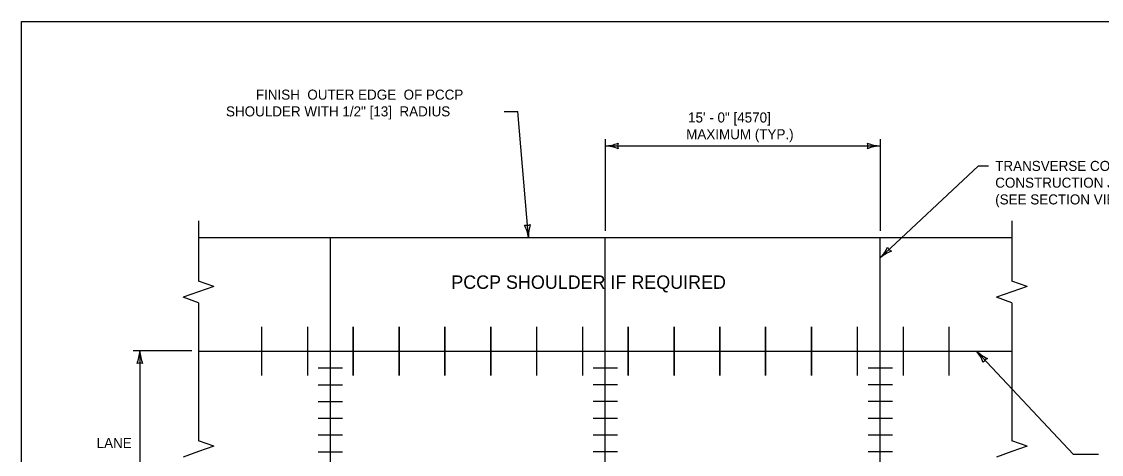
# Model space of a CAD drawing. Extents: x 49979.1 to 50021, y 49966.7 to 50011.4.
# Drawn here: x 49999.38 to 50005.83, y 49996.41 to 49999 of the extents above; entities that cross this region are included whole.
import ezdxf

# ---------------------------------------------------------------- set-up
doc = ezdxf.new("R2010")
doc.units = 0
for name, color, linetype in [('Level 1', 7, 'Continuous'), ('Level 2', 7, 'Continuous'), ('Level 20', 7, 'Continuous'), ('Level 3', 7, 'Continuous'), ('Level 4', 7, 'Continuous'), ('Level 6', 7, 'Continuous')]:
    doc.layers.add(name, color=color, linetype=linetype)

msp = doc.modelspace()

# ---------------------------------------------------------------- linework, layer by layer
at = {"layer": 'Level 1'}
for p, q in [((50000.4413, 49997.7101), (50005.3002, 49997.7101)), ((50001.228, 49993.431), (50001.228, 49997.7101)), ((50002.8704, 49993.431), (50002.8704, 49997.7101)), ((50004.5127, 49993.431), (50004.5127, 49997.7101)), ((50000.4398, 49997.0314), (50005.2994, 49997.0314))]:
    msp.add_line(p, q, dxfattribs=at)
msp.add_lwpolyline([(49999.3835, 49998.9992), (50016.7501, 49998.9992), (50016.7501, 49987.7988), (49999.3835, 49987.7988)], close=True, dxfattribs=at)
at = {"layer": 'Level 3'}
for p, q in [((50002.267, 49998.4631), (50002.347, 49998.4631)), ((50002.4114, 49997.7116), (50002.347, 49998.4631)), ((50002.8704, 49998.2967), (50002.8704, 49997.7501)), ((50004.5131, 49998.2967), (50004.5131, 49997.7501)), ((50002.8704, 49998.2567), (50004.5131, 49998.2567)), ((50004.5127, 49997.5884), (50005.0994, 49998.1374)), ((50005.0994, 49998.1374), (50005.1598, 49998.1374)), ((50000.3998, 49997.0329), (50000.0498, 49997.0329)), ((50000.0898, 49997.0329), (50000.0898, 49995.8323)), ((50005.0885, 49997.0314), (50005.6674, 49996.4148)), ((50005.8161, 49996.4148), (50005.6674, 49996.4148))]:
    msp.add_line(p, q, dxfattribs=at)
for centre, radius, start, end in [((50002.8589, 49998.4894), 0.233, 272.82731, 292.07716), ((50002.8612, 49998.0346), 0.2223, 67.45601, 87.63952), ((50002.9986, 49998.2567), 0.0548, 162.13882, 197.86118), ((50004.5222, 49998.4789), 0.2223, 247.45601, 267.63952), ((50004.3849, 49998.2567), 0.0548, 342.13882, 17.86118), ((50004.5246, 49998.024), 0.233, 92.82731, 112.07716), ((50002.4006, 49997.8378), 0.0548, 257.03091, 292.75327), ((50002.1806, 49997.6788), 0.233, 7.7194, 26.96925), ((50002.6336, 49997.7199), 0.2223, 162.3481, 182.53161), ((50004.3453, 49997.7504), 0.233, 315.92832, 335.17817), ((50004.6064, 49997.676), 0.0548, 205.23983, 240.96219), ((50004.6578, 49997.4199), 0.2223, 110.55702, 130.74053), ((49999.8676, 49997.042), 0.2223, 337.45601, 357.63952), ((50000.3225, 49997.0444), 0.233, 182.82731, 202.07716), ((50004.9202, 49996.8861), 0.2223, 20.64669, 40.8302), ((50005.2503, 49997.1991), 0.233, 226.01799, 245.26784), ((50000.0898, 49996.9047), 0.0548, 72.13882, 107.86118), ((50005.1762, 49996.938), 0.0548, 115.3295, 151.05186)]:
    msp.add_arc(centre, radius, start, end, dxfattribs=at)
at = {"layer": 'Level 4'}
for p, q in [((50000.8175, 49997.1774), (50000.8175, 49996.8854)), ((50001.0913, 49997.1774), (50001.0913, 49996.8854)), ((50001.365, 49996.8854), (50001.365, 49997.1774)), ((50001.365, 49997.1774), (50001.365, 49996.8854)), ((50001.6387, 49996.8854), (50001.6387, 49997.1774)), ((50001.6387, 49997.1774), (50001.6387, 49996.8854)), ((50001.9124, 49996.8854), (50001.9124, 49997.1774)), ((50001.9124, 49997.1774), (50001.9124, 49996.8854)), ((50002.1861, 49996.8854), (50002.1861, 49997.1774)), ((50002.1861, 49997.1774), (50002.1861, 49996.8854)), ((50002.4598, 49997.1774), (50002.4598, 49996.8854)), ((50002.7336, 49997.1774), (50002.7336, 49996.8854)), ((50003.0073, 49996.8854), (50003.0073, 49997.1774)), ((50003.0073, 49997.1774), (50003.0073, 49996.8854)), ((50003.281, 49996.8854), (50003.281, 49997.1774)), ((50003.281, 49997.1774), (50003.281, 49996.8854)), ((50003.5547, 49996.8854), (50003.5547, 49997.1774)), ((50003.5547, 49997.1774), (50003.5547, 49996.8854)), ((50003.8284, 49996.8854), (50003.8284, 49997.1774)), ((50003.8284, 49997.1774), (50003.8284, 49996.8854)), ((50004.1021, 49996.8854), (50004.1021, 49997.1774)), ((50004.1021, 49997.1774), (50004.1021, 49996.8854)), ((50004.3759, 49997.1774), (50004.3759, 49996.8854)), ((50004.6496, 49997.1774), (50004.6496, 49996.8854)), ((50004.9233, 49997.1774), (50004.9233, 49996.8854)), ((50001.155, 49996.9309), (50001.301, 49996.9309)), ((50002.7974, 49996.9319), (50002.9434, 49996.9319)), ((50004.4398, 49996.9319), (50004.5857, 49996.9319)), ((50001.155, 49996.8309), (50001.301, 49996.8309)), ((50002.7974, 49996.8319), (50002.9434, 49996.8319)), ((50004.4398, 49996.8319), (50004.5857, 49996.8319)), ((50001.155, 49996.7308), (50001.301, 49996.7308)), ((50002.7974, 49996.7319), (50002.9434, 49996.7319)), ((50004.4398, 49996.7319), (50004.5857, 49996.7319)), ((50001.155, 49996.6308), (50001.301, 49996.6308)), ((50002.7974, 49996.6318), (50002.9434, 49996.6318)), ((50004.4398, 49996.6318), (50004.5857, 49996.6318)), ((50001.155, 49996.5307), (50001.301, 49996.5307)), ((50002.7974, 49996.5318), (50002.9434, 49996.5318)), ((50004.4398, 49996.5318), (50004.5857, 49996.5318)), ((50001.155, 49996.4306), (50001.301, 49996.4306)), ((50002.7974, 49996.4317), (50002.9434, 49996.4317)), ((50004.4398, 49996.4317), (50004.5857, 49996.4317))]:
    msp.add_line(p, q, dxfattribs=at)
at = {"layer": 'Level 6'}
for p, q in [((50000.4398, 49997.8101), (50000.4398, 49997.4499)), ((50005.2986, 49997.8101), (50005.2986, 49997.4499)), ((50000.5312, 49997.4175), (50000.4398, 49997.4499)), ((50005.39, 49997.4175), (50005.2986, 49997.4499)), ((50000.4398, 49997.3851), (50000.3484, 49997.3527)), ((50000.5312, 49997.4175), (50000.4398, 49997.3851)), ((50005.2986, 49997.3851), (50005.2072, 49997.3527)), ((50005.39, 49997.4175), (50005.2986, 49997.3851)), ((50000.4398, 49997.3203), (50000.3484, 49997.3527)), ((50000.4398, 49997.3203), (50000.4398, 49996.4964)), ((50005.2986, 49997.3203), (50005.2072, 49997.3527)), ((50005.2986, 49997.3203), (50005.2986, 49996.4964)), ((50000.5312, 49996.464), (50000.4398, 49996.4964)), ((50005.39, 49996.464), (50005.2986, 49996.4964)), ((50000.4398, 49996.4316), (50000.3484, 49996.3992)), ((50000.5312, 49996.464), (50000.4398, 49996.4316)), ((50005.2986, 49996.4316), (50005.2072, 49996.3992)), ((50005.39, 49996.464), (50005.2986, 49996.4316))]:
    msp.add_line(p, q, dxfattribs=at)

# ---------------------------------------------------------------- texts
at = {"layer": 'Level 2'}
for s, p in [('FINISH  OUTER EDGE  OF PCCP', (50000.783, 49998.5331)), ('SHOULDER WITH 1/2" [13]  RADIUS', (50000.6047, 49998.4331)), ('15\' - 0" [4570]', (50003.3649, 49998.3967)), ('MAXIMUM (TYP.)', (50003.3535, 49998.2967)), ('TRANSVERSE CONTRACTION OR', (50005.1998, 49998.1074)), ('CONSTRUCTION JOINT (TYP.)', (50005.1998, 49998.0074)), ('(SEE SECTION VIEWS)', (50005.1998, 49997.9074)), ('LANE', (49999.8318, 49996.4526))]:
    msp.add_text(s, height=0.06, dxfattribs=at).set_placement(p)
at = {"layer": 'Level 20'}
msp.add_text('PCCP SHOULDER IF REQUIRED', height=0.08, dxfattribs=at).set_placement((50001.9504, 49997.4034))

doc.saveas('drawing.dxf')
